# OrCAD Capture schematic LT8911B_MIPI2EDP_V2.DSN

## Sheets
1 LT8911B: size A2
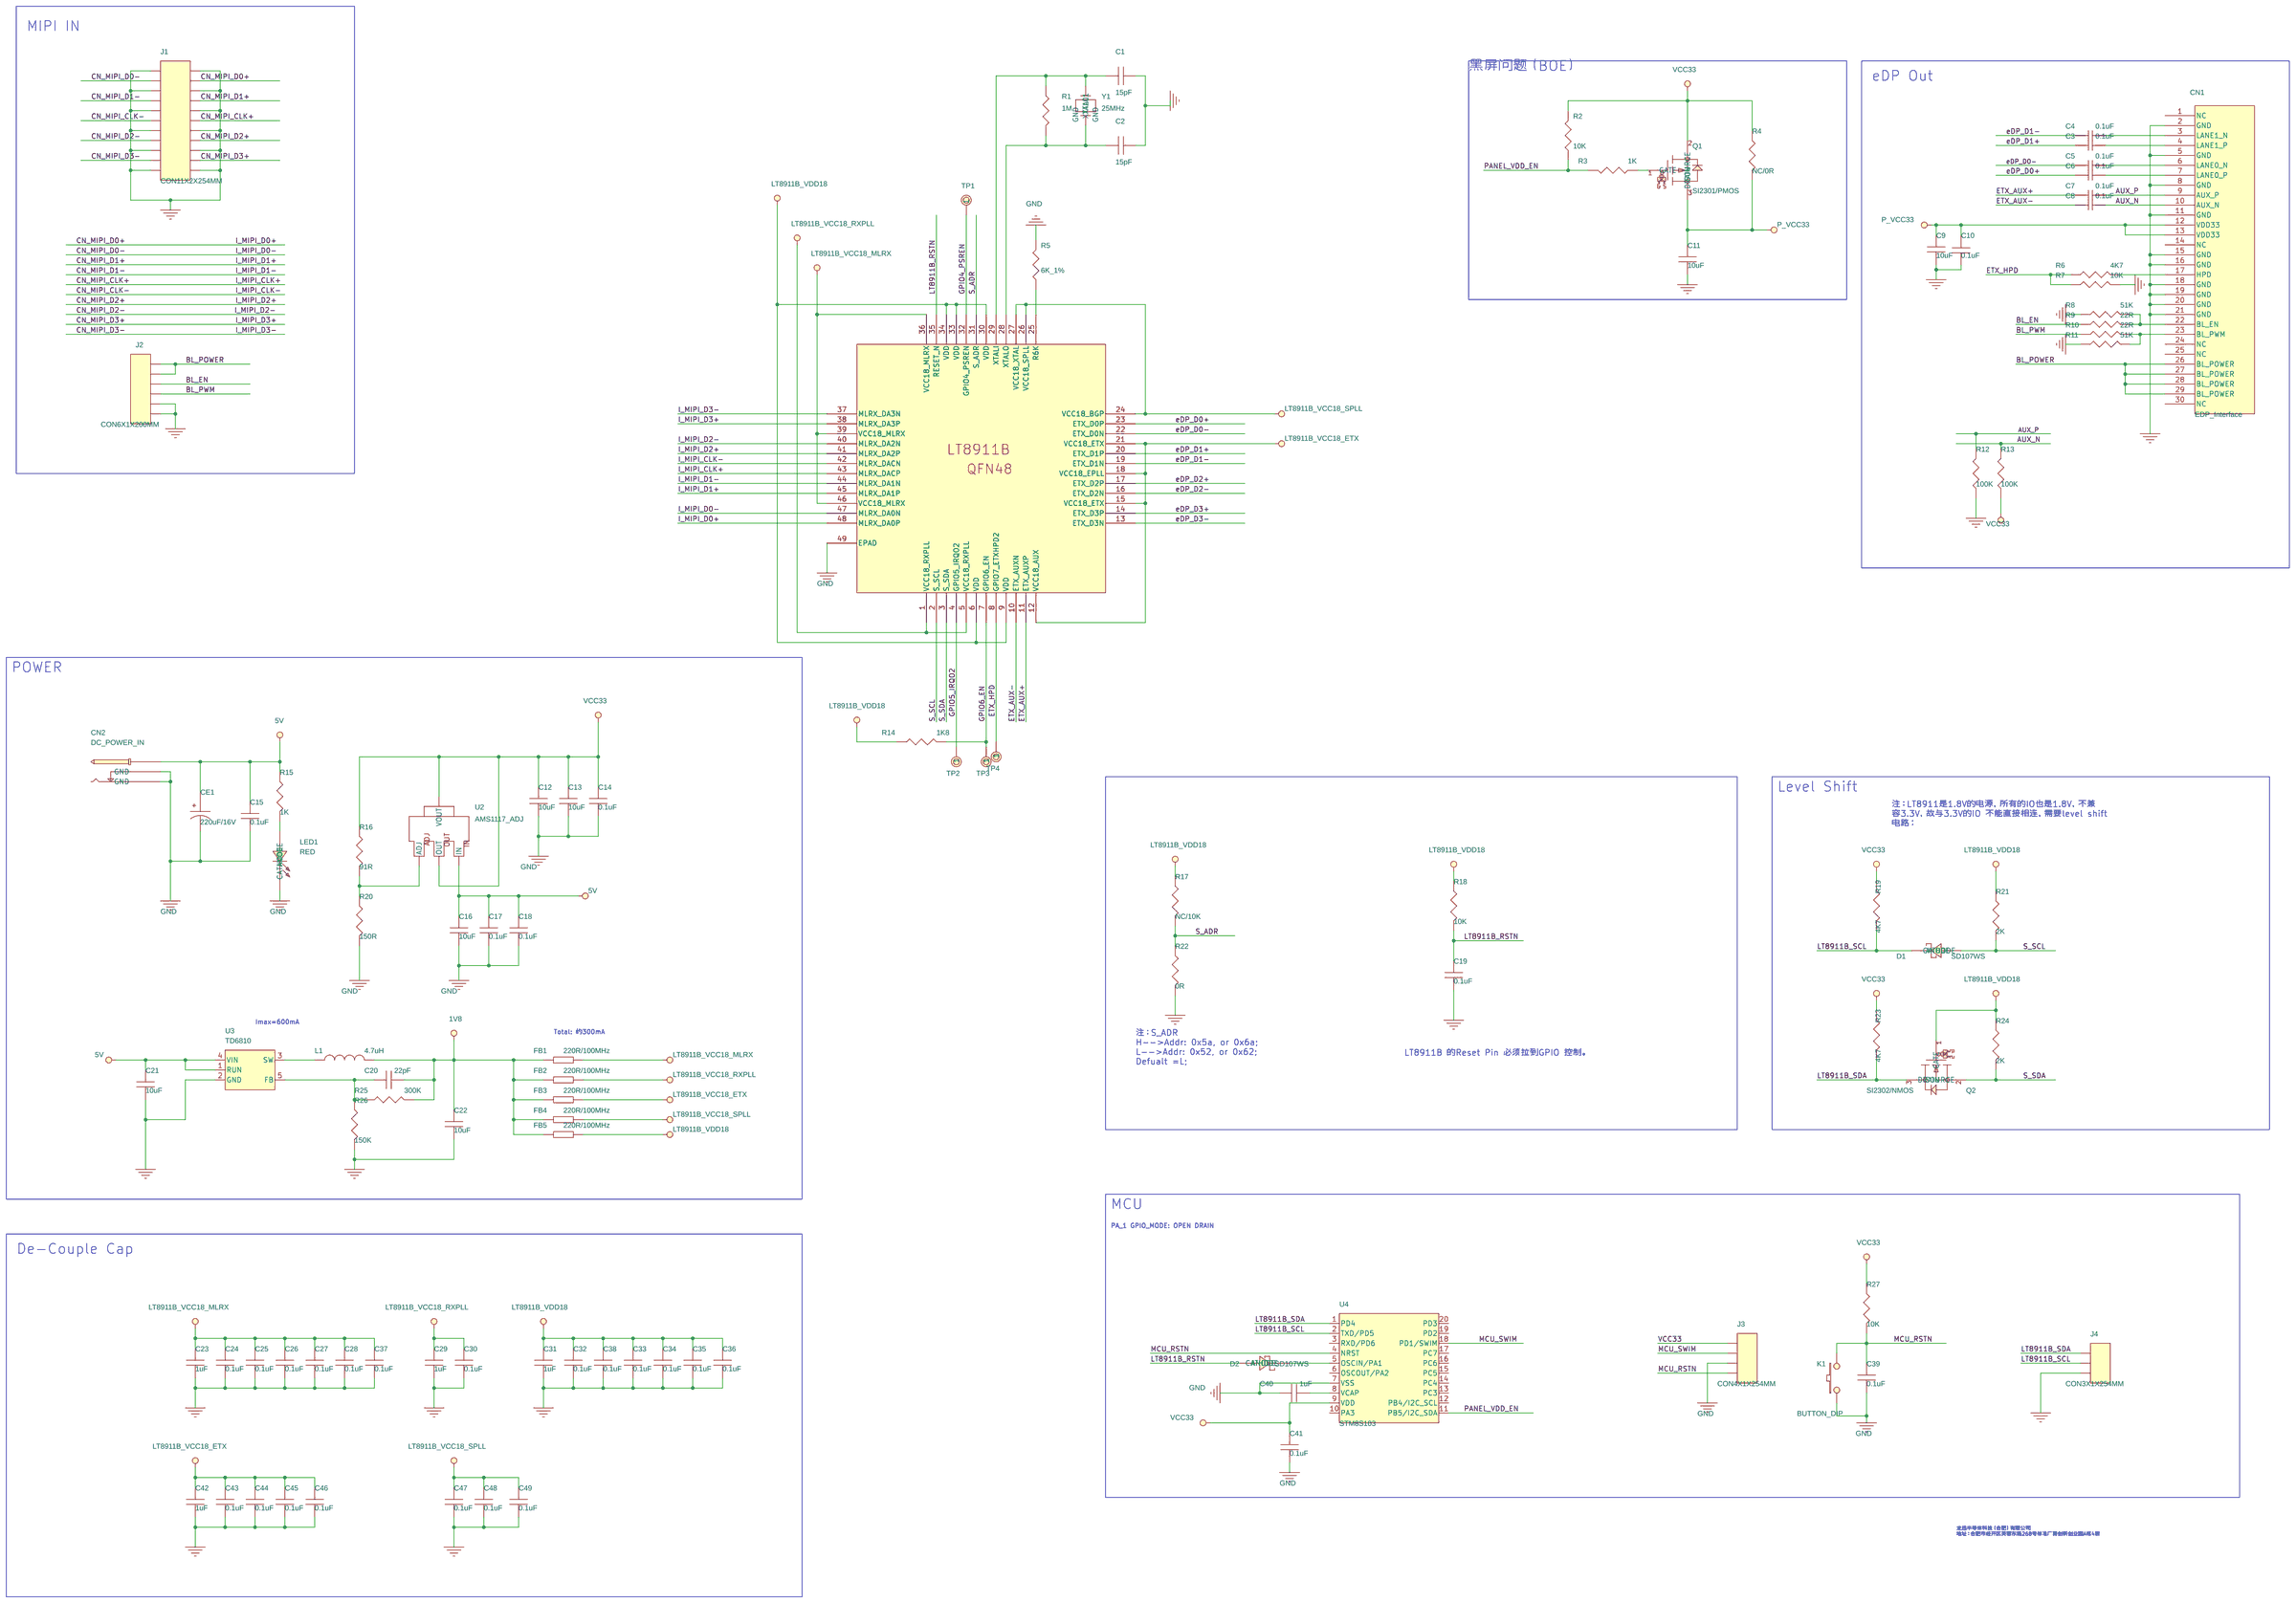
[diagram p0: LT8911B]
2 History
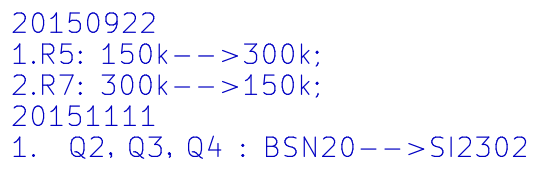
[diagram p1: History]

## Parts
C1  15pF  [0603-C]
C2  15pF  [0603-C]
C3  0.1uF  [0402-C]
C4  0.1uF  [0402-C]
C5  0.1uF  [0402-C]
C6  0.1uF  [0402-C]
C7  0.1uF  [0402-C]
C8  0.1uF  [0402-C]
C9  10uF  [0603-C]
C10  0.1uF  [0603-C]
C11  10uF  [0603-C]
C12  10uF  [0603-C]
C13  10uF  [0603-C]
C14  0.1uF  [0603-C]
C15  0.1uF  [0603-C]
C16  10uF  [0603-C]
C17  0.1uF  [0603-C]
C18  0.1uF  [0603-C]
C19  0.1uF  [0603-C]
C20  22pF  [0603-C]
C21  10uF  [0603-C]
C22  10uF  [0603-C]
C23  1uF  [0603-C]
C24  0.1uF  [0603-C]
C25  0.1uF  [0603-C]
C26  0.1uF  [0603-C]
C27  0.1uF  [0603-C]
C28  0.1uF  [0603-C]
C29  1uF  [0603-C]
C30  0.1uF  [0603-C]
C31  1uF  [0603-C]
C32  0.1uF  [0603-C]
C33  0.1uF  [0603-C]
C34  0.1uF  [0603-C]
C35  0.1uF  [0603-C]
C36  0.1uF  [0603-C]
C37  0.1uF  [0603-C]
C38  0.1uF  [0603-C]
C39  0.1uF  [0603-C]
C40  1uF  [0603-C]
C41  0.1uF  [0603-C]
C42  1uF  [0603-C]
C43  0.1uF  [0603-C]
C44  0.1uF  [0603-C]
C45  0.1uF  [0603-C]
C46  0.1uF  [0603-C]
C47  0.1uF  [0603-C]
C48  0.1uF  [0603-C]
C49  0.1uF  [0603-C]
CE1  220uF/16V  [CD7_3MM]
CN1  EDP_Interface
CN2  DC_POWER_IN  [DC005]
D1  SD107WS  [SD107WS_SOD-323]
D2  SD107WS  [SD107WS_SOD-323]
FB1  220R/100MHz  [0603-FB]
FB2  220R/100MHz  [0603-FB]
FB3  220R/100MHz  [0603-FB]
FB4  220R/100MHz  [0603-FB]
FB5  220R/100MHz  [0603-FB]
J1  CON11X2X254MM  [CON11X2X254MM]
J2  CON6X1X200MM  [CON6X1X200MM]
J3  CON4X1X254MM  [CON4X1X254MM]
J4  CON3X1X254MM  [CON3X1X254MM]
K1  BUTTON_DIP  [BUTTON_DIP]
L1  4.7uH  [CD43]
LED1  RED  [0603-LED]
Q1  SI2301/PMOS  [SI2301_SOT23]
Q2  SI2302/NMOS  [SI2302_SOT23]
R1  1M  [0603-R]
R2  10K  [0603-R]
R3  1K  [0603-R]
R4  NC/0R  [0603-R]
R5  6K_1%  [0603-R]
R6  4K7  [0603-R]
R7  10K  [0603-R]
R8  51K  [0603-R]
R9  22R  [0603-R]
R10  22R  [0603-R]
R11  51K  [0603-R]
R12  100K  [0603-R]
R13  100K  [0603-R]
R14  1K8  [0603-R]
R15  1K  [0603-R]
R16  91R  [0603-R]
R17  NC/10K  [0603-R]
R18  10K  [0603-R]
R19  4K7  [0603-R]
R20  150R  [0603-R]
R21  2K  [0603-R]
R22  0R  [0603-R]
R23  4K7  [0603-R]
R24  2K  [0603-R]
R25  300K  [0603-R]
R26  150K  [0603-R]
R27  10K  [0603-R]
TP1  tp  [TP1.5-TOP]
TP2  tp  [TP1.5-TOP]
TP3  tp  [TP1.5-TOP]
TP4  tp  [TP1.5-TOP]
U1  LT8911B  [LT8911B_QFN48_EPAD]
U2  AMS1117_ADJ  [AMS1117_ADJ_SOT-223_4]
U3  TD6810  [TD6810_SOT23-5]
U4  STM8S103  [STM8S103_TSSOP20]
Y1  25MHz  [CRY_3225]

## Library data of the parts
C1 C2 = CAP_NP0603: PCB Footprint Status: Checked; Part Number: 117-00-3002; Part Status: On Hand; Part Type: CAPACITOR; Price: 0.0072; Purchase Information: 13510796878 伊美尔电子; Standard PCB Footprint: 0603
C3-C8 = CAP_NP0402: Part Number: 117-00-3044
C9 C11-C13 C16 C21 C22 = CAP_NP0603: PCB Footprint Status: Checked; Part Number: 117-00-3043; Part Status: On Hand; Part Type: CAPACITOR; Price: 0.1; Purchase Information: 13510796878 伊美尔电子; Standard PCB Footprint: 0603
C10 C14 C15 C17 C18 C39 C41 = CAP_NP0603: PCB Footprint Status: Checked; Part Number: 117-00-3036; Part Status: On Hand; Part Type: CAPACITOR; Price: 0.0072; Purchase Information: 13510796878 伊美尔电子; Standard PCB Footprint: 0603
C19 C24-C28 C30 C32-C38 C43-C49 = CAP_NP0603: Part Number: 117-00-3036; Part Type: CAPACITOR
C20 = CAP_NP0603: PCB Footprint Status: Checked; Part Number: 117-00-3003; Part Status: On Hand; Part Type: CAPACITOR; Price: 0.0072; Purchase Information: 13510796878 伊美尔电子; Standard PCB Footprint: 0603
C23 C29 C31 C42 = CAP_NP0603: Part Number: 117-00-3040; Part Type: CAPACITOR
C40 = CAP_NP0603: PCB Footprint Status: Checked; Part Number: 117-00-3040; Part Status: On Hand; Part Type: CAPACITOR; Price: 0.0072; Purchase Information: 13510796878 伊美尔电子; Standard PCB Footprint: 0603
CE1 = ECAP_POL: Part Number: 117-00-3057; Part Status: On Hand; Part Type: ELECTROLYSIS CAPACITOR; Price: 0.0738; Purchase Information: 15914148925 腾光达电子
CN1 = EDP_Connector
CN2 = DC005: Part Description: DC JACK,DC005; Part Number: 226-00-3088; Part Status: On Hand; Part Type: JACK; Price: 0.2; Purchase Information: 18969723602 乐清市鑫皖电子
D1 D2 = SD107WS: Part Number: 647-01-3117
FB1-FB5 = BEAD0603: PCB Footprint Status: Checked; Part Number: 647-01-3069; Part Status: On Hand; Part Type: BEAD; Price: 0.011; Purchase Information: 07558255526 小商行电子; Standard PCB Footprint: 0603
J1 = CON11X2X254MM: PCB Footprint Status: Checked; Part Number: 226-00-3050; Part Status: On Hand; Part Type: CONNECTOR; Price: 0; Purchase Information: 13714111152 福强电子科技 朱先生; Standard PCB Footprint: 11*2*2.54MM
J2 = CON6X1X200MM: Part Number: 226-00-3025
J3 = CON4X1X254MM: PCB Footprint Status: Checked; Part Number: 226-00-3003; Part Status: On Hand; Part Type: CONNECTOR; Price: 0; Purchase Information: 13714111152 福强电子科技 朱先生; Standard PCB Footprint: 4*1*2.54MM
J4 = CON3X1X254MM: Part Number: 226-00-3002
K1 = BUTTON: PCB Footprint Status: Checked; Part Number: 647-00-3033; Part Status: On Hand; Price: 0.1; Purchase Information: 15996744099 江苏泗阳九九电子
L1 = INDUCTOR0805: Data Sheet: CD43.pdf; PCB Footprint Status: Checked; Part Number: 647-00-3084; Part Status: Not On Hand; Part Type: INDUCTOR; Price: 0.2; Purchase Information: 15920002410 深圳宝创达
LED1 = LED0603: PCB Footprint Status: Checked; Part Description: red; Part Number: 647-00-3064; Part Status: On Hand; Part Type: LED; Price: 0.04; Purchase Information: 021-53081803 上海荣达威电子
Q1 = SI2301: Part Number: 647-00-3037
Q2 = SI2302: Part Number: 647-00-3013
R1 = RES0603: PCB Footprint Status: Checked; Part Number: 737-00-3074; Part Status: On Hand; Part Type: RESISTOR; Price: 0.0028; Purchase Information: 13510796878 伊美尔电子; Standard PCB Footprint: 0603; Tolerance: %5
R2-R4 R6-R13 = RES0603: Part Number: 737-00-3061
R5 R27 = RES0603: PCB Footprint Status: Checked; Part Number: 737-00-3049; Part Status: On Hand; Part Type: RESISTOR; Price: 0.0028; Purchase Information: 13510796878 伊美尔电子; Standard PCB Footprint: 0603; Tolerance: %5
R14 = RES0603: Part Number: 737-00-3035
R15 = RES0603: PCB Footprint Status: Checked; Part Number: 737-00-3032; Part Status: On Hand; Part Type: RESISTOR; Price: 0.0028; Purchase Information: 13510796878 伊美尔电子; Standard PCB Footprint: 0603; Tolerance: %5
R16 = RES0603: PCB Footprint Status: Checked; Part Number: 737-00-3016; Part Status: On Hand; Part Type: RESISTOR; Price: 0.0028; Purchase Information: 13510796878 伊美尔电子; Standard PCB Footprint: 0603; Tolerance: %5
R17 R18 = RES0603: Part Number: 737-00-3049
R19 R23 = RES0603: Part Number: 737-00-3042
R20 = RES0603: PCB Footprint Status: Checked; Part Number: 737-00-3019; Part Status: On Hand; Part Type: RESISTOR; Price: 0.0028; Purchase Information: 13510796878 伊美尔电子; Standard PCB Footprint: 0603; Tolerance: %5
R21 R24 = RES0603: Part Number: 737-00-3036
R22 = RES0603: Part Number: 737-00-3110
R25 = RES0603: PCB Footprint Status: Checked; Part Number: 737-00-3068; Part Status: On Hand; Part Type: RESISTOR; Price: 0.0028; Purchase Information: 13510796878 伊美尔电子; Standard PCB Footprint: 0603; Tolerance: %5
R26 = RES0603: PCB Footprint Status: Checked; Part Number: 737-00-3070; Part Status: On Hand; Part Type: RESISTOR; Price: 0.0028; Purchase Information: 13510796878 伊美尔电子; Standard PCB Footprint: 0603; Tolerance: %5
TP1-TP4 = TESTPOINT-D10
U1 = LT8911B
U2 = AMS1117_ADJ: Data Sheet: AMS1117_ADJ.pdf; Part Description: AMS1117-ADJ; Part Number: 427-00-3008; Part Status: On Hand; Part Type: REGULATOR; Price: 0.3; Purchase Information: 0755-83229575陈; Standard PCB Footprint: SOT-223
U3 = TD6810: Data Sheet: TD6810.pdf; Part Number: 427-00-3007; Part Status: On Hand; Part Type: REGULATOR; Price: 0.5; Purchase Information: 13632959229 深圳伟达电子  张小姐; Standard PCB Footprint: SOT23-5
U4 = STM8S103_TSSOP20: Data Sheet: STM8S103.pdf; PCB Footprint Status: Checked; Part Number: 628-00-3001; Part Status: On Hand; Part Type: MCU; Price: 0; Standard PCB Footprint: TSSOP20
Y1 = CRYSTAL_4PIN: Data Sheet: CRYSTAL_4PIN.pdf; PCB Footprint Status: Checked; Part Description: 4 pin, passive; Part Number: 647-00-3038; Part Status: On Hand; Part Type: CRYSTAL; Price: 1; Purchase Information: 0755-83609566 华瑞纳电子; Standard PCB Footprint: LLC

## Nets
1V8: C20.2 C22.1 FB1.1 FB2.1 FB3.1 FB4.1 FB5.1 L1.2 R25.2
5V: C15.1 C16.1 C17.1 C18.1 C21.1 CE1.1 CN2.2 R15.1 U2.3(IN) U3.1(RUN) U3.4(VIN)
GND: C1.1 C2.1 C9.2 C10.1 C11.2 C12.2 C13.2 C14.2 C15.2 C16.2 C17.2 C18.2 C19.2 C21.2 C22.2 C23.2 C24.2 C25.2 C26.2 C27.2 C28.2 C29.2 C30.2 C31.2 C32.2 C33.2 C34.2 C35.2 C36.2 C37.2 C38.2 C39.2 C40.1 C41.2 C42.2 C43.2 C44.2 C45.2 C46.2 C47.2 C48.2 C49.2 CE1.2 CN1.2(GND) CN1.5(GND) CN1.8(GND) CN1.11(GND) CN1.15(GND) CN1.16(GND) CN1.18(GND) CN1.19(GND) CN1.20(GND) CN1.21(GND) CN2.1(GND) CN2.3(GND) J1.1 J1.2 J1.5 J1.6 J1.9 J1.10 J1.13 J1.14 J1.17 J1.18 J1.21 J1.22 J2.5 J2.6 J3.3 J4.3 K1.1 LED1.C(CATHODE) R5.2 R7.2 R8.1 R11.1 R12.1 R20.2 R22.2 R26.2 U1.49(EPAD) U3.2(GND) U4.7(VSS) Y1.2(GND) Y1.4(GND)
VCC33: C12.1 C13.1 C14.1 C41.1 J3.1 Q1.S(SOURCE) R2.2 R4.1 R13.1 R16.1 R19.1 R23.1 R27.1 U2.2(OUT) U2.4(VOUT) U4.9(VDD)
AUX_N: C8.2 CN1.10(AUX_N) R13.2
AUX_P: C7.2 CN1.9(AUX_P) R12.2
BL_EN: J2.3 R9.1
BL_POWER: CN1.26(BL_POWER) CN1.27(BL_POWER) CN1.28(BL_POWER) CN1.29(BL_POWER) J2.1 J2.2
BL_PWM: J2.4 R10.1
CN_MIPI_CLK+: J1.12 U1.43(MLRX_DACP)
CN_MIPI_CLK-: J1.11 U1.42(MLRX_DACN)
CN_MIPI_D0+: J1.4 U1.48(MLRX_DA0P)
CN_MIPI_D0-: J1.3 U1.47(MLRX_DA0N)
CN_MIPI_D1+: J1.8 U1.45(MLRX_DA1P)
CN_MIPI_D1-: J1.7 U1.44(MLRX_DA1N)
CN_MIPI_D2+: J1.16 U1.41(MLRX_DA2P)
CN_MIPI_D2-: J1.15 U1.40(MLRX_DA2N)
CN_MIPI_D3+: J1.20 U1.38(MLRX_DA3P)
CN_MIPI_D3-: J1.19 U1.37(MLRX_DA3N)
eDP_D0+: C6.1 U1.23(ETX_D0P)
eDP_D0-: C5.1 U1.22(ETX_D0N)
eDP_D1+: C3.1 U1.20(ETX_D1P)
eDP_D1-: C4.1 U1.19(ETX_D1N)
eDP_D2+: U1.17(ETX_D2P)
eDP_D2-: U1.16(ETX_D2N)
eDP_D3+: U1.14(ETX_D3P)
eDP_D3-: U1.13(ETX_D3N)
ETX_AUX+: C7.1 U1.11(ETX_AUXP)
ETX_AUX-: C8.1 U1.10(ETX_AUXN)
ETX_HPD: R6.1 R7.1 TP4.1 U1.8(GPIO7_ETXHPD2)
GPIO4_PSREN: TP1.1 U1.32(GPIO4_PSREN)
GPIO5_IRQO2: TP2.1 U1.4(GPIO5_IRQO2)
GPIO6_EN: R14.2 TP3.1 U1.7(GPIO6_EN)
LT8911B_RSTN: C19.1 D2.A(ANODE) R18.2 U1.35(RESET_N)
LT8911B_SCL: D1.C(CATHODE) J4.2 R19.2 U4.2(TXD/PD5)
LT8911B_SDA: J4.1 Q2.D(DRAIN) R23.2 U4.1(PD4)
LT8911B_VCC18_ETX: C42.1 C43.1 C44.1 C45.1 C46.1 FB3.2 U1.12(VCC18_AUX) U1.15(VCC18_ETX) U1.18(VCC18_EPLL) U1.21(VCC18_ETX)
LT8911B_VCC18_MLRX: C23.1 C24.1 C25.1 C26.1 C27.1 C28.1 C37.1 FB1.2 U1.36(VCC18_MLRX) U1.39(VCC18_MLRX) U1.46(VCC18_MLRX)
LT8911B_VCC18_RXPLL: C29.1 C30.1 FB2.2 U1.1(VCC18_RXPLL) U1.5(VCC18_RXPLL)
LT8911B_VCC18_SPLL: C47.1 C48.1 C49.1 FB4.2 U1.24(VCC18_BGP) U1.26(VCC18_SPLL) U1.27(VCC18_XTAL)
LT8911B_VDD18: C31.1 C32.1 C33.1 C34.1 C35.1 C36.1 C38.1 FB5.2 Q2.G(GATE) R14.1 R17.1 R18.1 R21.1 R24.1 U1.6(VDD) U1.9(VDD) U1.30(VDD) U1.33(VDD) U1.34(VDD)
MCU_RSTN: C39.1 J3.4 K1.2 R27.2 U4.4(NRST)
MCU_SWIM: J3.2 U4.18(PD1/SWIM)
NC: CN1.1(NC) CN1.14(NC) CN1.24(NC) CN1.25(NC) CN1.30(NC)
P_VCC33: C9.1 C10.2 C11.1 CN1.12(VDD33) CN1.13(VDD33) Q1.D(DRAIN) R4.2
PANEL_VDD_EN: R2.1 R3.2 U4.11(PB5/I2C_SDA)
S_ADR: R17.2 R22.1 U1.31(S_ADR)
S_SCL: D1.A(ANODE) R21.2 U1.2(S_SCL)
S_SDA: Q2.S(SOURCE) R24.2 U1.3(S_SDA)
N16979564: CN1.17(HPD) R6.2
N16979740: CN1.22(BL_EN) R8.2 R9.2
N16979758: CN1.23(BL_PWM) R10.2 R11.2
N16979794: C3.2 CN1.4(LANE1_P)
N16979796: C4.2 CN1.3(LANE1_N)
N16979842: C5.2 CN1.6(LANE0_N)
N16979844: C6.2 CN1.7(LANE0_P)
N16979922: Q1.G(GATE) R3.1
N16984476: LED1.A(ANODE) R15.2
N16984615: C20.1 R25.1 R26.1 U3.5(FB)
N16984619: L1.1 U3.3(SW)
N16984886: R16.2 R20.1 U2.1(ADJ)
N16988420: C1.2 R1.2 U1.29(XTALI) Y1.1(XTAL0)
N16988423: C2.2 R1.1 U1.28(XTALO) Y1.3(XTAL1)
N16988509: R5.1 U1.25(R6K)
N16992095: D2.C(CATHODE) U4.5(OSCIN/PA1)
N16992132: C40.2 U4.8(VCAP)

Not connected (* = marked no-connect by the designer): U4 3(RXD/PD6) 6(OSCOUT/PA2) 10(PA3) 12(PB4/I2C_SCL) 13(PC3) 14(PC4) 15(PC5) 16(PC6) 17(PC7) 19(PD2) 20(PD3)

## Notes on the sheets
sheet 1
- MIPI IN
- 黑屏问题（BOE）
- eDP Out
- POWER
- Level Shift
- 注：LT8911是1.8V的电源，所有的IO也是1.8V，不兼
  容3.3V，故与3.3V的IO 不能直接相连，需要level shift
  电路；
- Imax=600mA
- Total: 约300mA
- 注：S_ADR
  H-->Addr: 0x5a, or 0x6a;
  L-->Addr: 0x52, or 0x62;
  Defualt =L;
- LT8911B 的Reset Pin 必须拉到GPIO 控制。
- MCU
- PA_1 GPIO_MODE: OPEN DRAIN
- De-Couple Cap
- 龙迅半导体科技（合肥）有限公司
  地址：合肥市经开区芙蓉东路268号标准厂房创新创业园A栋4层
sheet 2
- 20150922
  1.R5: 150k-->300k;
  2.R7: 300k-->150k;
  20151111
  1.  Q2，Q3，Q4 : BSN20-->SI2302
